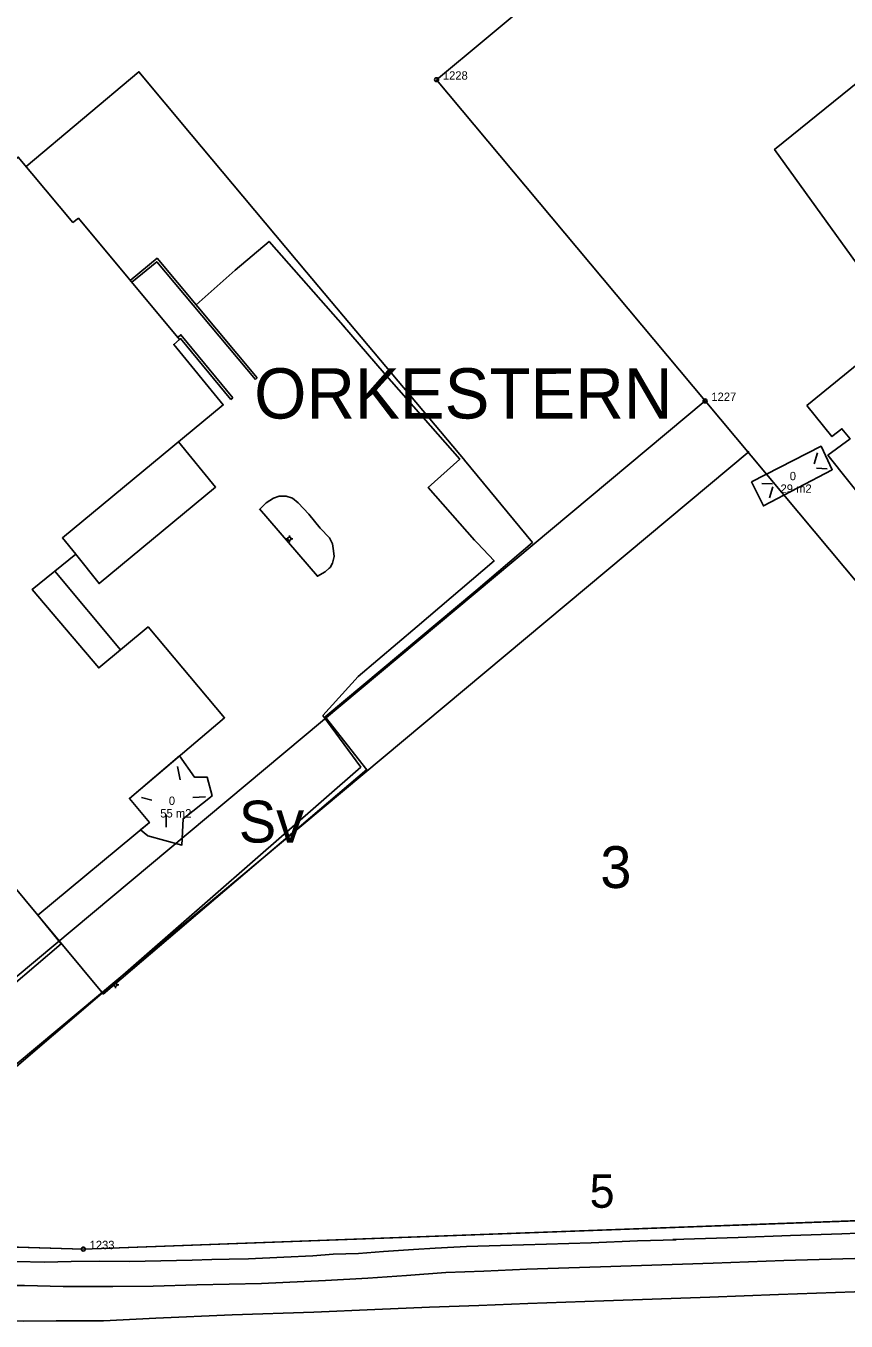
# Model space of a CAD drawing. Extents: x 1517693 to 1518189, y 6494860 to 6495280.
# Drawn here: x 1517838.6 to 1517936.6, y 6494947.7 to 6495102.4 of the extents above; entities that cross this region are included whole.
import ezdxf

# ---------------------------------------------------------------- set-up
doc = ezdxf.new("R2010")
doc.units = 0
for name, color, linetype in [('adress', 7, 'Continuous'), ('allmanbygg_symbollinje', 7, 'Continuous'), ('allmanbyggnad', 7, 'Continuous'), ('allmanbyggnad_nummer', 7, 'Continuous'), ('byggnad_areatext', 7, 'Continuous'), ('fastighetsbeteckning', 7, 'Continuous'), ('gc_vag', 7, 'Continuous'), ('grans', 7, 'Continuous'), ('granspunkt', 7, 'Continuous'), ('granspunkt_text', 7, 'Continuous'), ('kvartersgrans', 7, 'Continuous'), ('kvartersnamn', 7, 'Continuous'), ('parkeringskant', 7, 'Continuous'), ('planteringskant', 7, 'Continuous'), ('rattighet_grans_ANV_EJ', 7, 'Continuous'), ('skarmtak', 7, 'Continuous'), ('staket', 7, 'Continuous'), ('stenmur', 7, 'Continuous'), ('stolpe_belysning', 7, 'Continuous'), ('sv_text', 7, 'Continuous'), ('vagkant', 7, 'Continuous'), ('vagkant_mindre', 7, 'Continuous')]:
    doc.layers.add(name, color=color, linetype=linetype)

msp = doc.modelspace()

# ---------------------------------------------------------------- linework, layer by layer
at = {"layer": 'allmanbygg_symbollinje'}
for p, q in [((1517933.16, 6495051.39), (1517932.74, 6495050.08)), ((1517933.04, 6495049.54), (1517934.3, 6495049.48)), ((1517926.51, 6495047.74), (1517927.77, 6495047.68)), ((1517927.83, 6495047.32), (1517927.41, 6495046)), ((1517856.72, 6495013.92), (1517857.04, 6495012.34)), ((1517852.41, 6495010.21), (1517853.68, 6495009.93)), ((1517860.05, 6495010.31), (1517858.55, 6495010.24)), ((1517855.39, 6495006.7), (1517855.36, 6495008.21))]:
    msp.add_line(p, q, dxfattribs=at)
at = {"layer": 'allmanbyggnad'}
for points in [[(1517795.98, 6495052.03), (1517837.72, 6495086.69), (1517844.24, 6495078.9), (1517844.89, 6495079.4), (1517856.96, 6495064.93), (1517856.28, 6495064.33), (1517862.19, 6495057.11), (1517842.98, 6495041.23), (1517844.57, 6495039.29), (1517839.38, 6495035.07), (1517847.33, 6495025.71), (1517853.22, 6495030.6), (1517862.35, 6495019.75), (1517850.98, 6495010.13), (1517853.38, 6495007.24), (1517840.06, 6494996.19), (1517822.37, 6495017.44), (1517823.84, 6495018.69), (1517795.97, 6495052.03)], [(1517931.88, 6495057.02), (1517968.08, 6495086.54)], [(1517941.88, 6495041.67), (1517934.38, 6495051.09), (1517937.03, 6495053.07), (1517936.06, 6495054.26), (1517934.86, 6495053.33), (1517931.87, 6495057.03)], [(1517925.25, 6495047.92), (1517933.58, 6495052.17), (1517934.9, 6495049.36), (1517926.69, 6495045.04), (1517925.25, 6495047.92)], [(1517850.98, 6495010.13), (1517856.98, 6495015.21), (1517858.75, 6495012.67), (1517860.26, 6495012.67), (1517860.86, 6495010.41), (1517857.4, 6495007.7), (1517857.25, 6495004.55), (1517853.2, 6495005.67), (1517852.31, 6495006.35), (1517853.38, 6495007.24), (1517850.98, 6495010.13)]]:
    msp.add_lwpolyline(points, dxfattribs=at)
at = {"layer": 'gc_vag'}
for points in [[(1517916.26, 6494957.41), (1517911.67, 6494957.3), (1517906.13, 6494957.05), (1517900.78, 6494956.88), (1517895.28, 6494956.74), (1517891.25, 6494956.6)], [(1517939.93, 6494958.28), (1517936.05, 6494958.14), (1517929.92, 6494957.93), (1517923.68, 6494957.69), (1517915.87, 6494957.44)], [(1517891.25, 6494956.6), (1517889.71, 6494956.53), (1517887.5, 6494956.42), (1517884.91, 6494956.25), (1517881.34, 6494956.04), (1517878.32, 6494955.79), (1517875.31, 6494955.69), (1517872.89, 6494955.51), (1517869.43, 6494955.34), (1517865.22, 6494955.16), (1517862.88, 6494955.09)], [(1517862.88, 6494955.09), (1517860.81, 6494955.05), (1517858.46, 6494954.98), (1517854.75, 6494954.91), (1517851, 6494954.84), (1517847.43, 6494954.88), (1517844.03, 6494954.84), (1517840.85, 6494954.74), (1517837.48, 6494954.81), (1517835.56, 6494954.81), (1517834.33, 6494954.91)], [(1517879.46, 6494952.85), (1517884.07, 6494953.16), (1517888.76, 6494953.52), (1517893.31, 6494953.69), (1517898.43, 6494953.9), (1517907.22, 6494954.18)], [(1517907.22, 6494954.18), (1517920.7, 6494954.64), (1517929.14, 6494954.95), (1517938.99, 6494955.23)], [(1517853.81, 6494951.88), (1517859.04, 6494952.04), (1517866.75, 6494952.18), (1517874.38, 6494952.57), (1517879.46, 6494952.85)], [(1517832.31, 6494947.99), (1517832.41, 6494949.71), (1517832.62, 6494951.11), (1517833.29, 6494951.63), (1517833.95, 6494951.95), (1517838.47, 6494951.95), (1517843.09, 6494951.84), (1517849.01, 6494951.84), (1517853.81, 6494951.88)]]:
    msp.add_lwpolyline(points, dxfattribs=at)
at = {"layer": 'grans'}
for p, q in [((1517942.78, 6495142.01), (1517887.66, 6495095.94)), ((1517919.72, 6495057.58), (1517887.66, 6495095.94)), ((1517807.17, 6494963.51), (1517919.72, 6495057.58)), ((1517993.72, 6494969.04), (1517919.72, 6495057.58)), ((1517845.48, 6494956.3), (1517968.3, 6494960.82)), ((1517833.61, 6494956.65), (1517845.48, 6494956.3))]:
    msp.add_line(p, q, dxfattribs=at)
at = {"layer": 'granspunkt'}
for centre in [(1517887.66, 6495095.94), (1517919.72, 6495057.58), (1517845.48, 6494956.3)]:
    msp.add_circle(centre, 0.237, dxfattribs=at)
at = {"layer": 'kvartersgrans'}
msp.add_lwpolyline([(1517810.53, 6494961.99), (1517821.9, 6494958.56), (1517833.61, 6494956.65), (1517845.48, 6494956.3), (1517968.3, 6494960.82), (1517976.46, 6494961.8), (1517984.36, 6494964.1), (1517991.77, 6494967.66)], dxfattribs=at)
at = {"layer": 'parkeringskant'}
msp.add_lwpolyline([(1517964.72, 6495092.99), (1517953.28, 6495108.07), (1517928.01, 6495087.61), (1517943.33, 6495066.36)], dxfattribs=at)
at = {"layer": 'planteringskant'}
msp.add_lwpolyline([(1517866.55, 6495044.64), (1517867.32, 6495045.43), (1517868.17, 6495045.97), (1517868.88, 6495046.21), (1517869.72, 6495046.2), (1517870.45, 6495045.97), (1517871.15, 6495045.43), (1517872.4, 6495044.06), (1517873.76, 6495042.4), (1517874.88, 6495041.24), (1517875.25, 6495040.5), (1517875.34, 6495039.67), (1517875.42, 6495039.01), (1517875.24, 6495038.21), (1517874.94, 6495037.7), (1517874.85, 6495037.62), (1517874.35, 6495037.18), (1517873.43, 6495036.64), (1517866.52, 6495044.68)], dxfattribs=at)
at = {"layer": 'rattighet_grans_ANV_EJ'}
msp.add_line((1517924.99, 6495051.56), (1517819.73, 6494963.58), dxfattribs=at)
at = {"layer": 'skarmtak'}
msp.add_line((1517842.08, 6495037.27), (1517849.92, 6495027.86), dxfattribs=at)
msp.add_lwpolyline([(1517856.86, 6495052.71), (1517861.28, 6495047.29), (1517847.36, 6495035.77), (1517844.54, 6495039.33)], dxfattribs=at)
at = {"layer": 'staket'}
for p, q in [((1517872.13, 6495072.97), (1517858.36, 6495089.39)), ((1517891.06, 6495050.42), (1517872.13, 6495072.97)), ((1517874.36, 6495019.87), (1517892.35, 6495034.9)), ((1517879.35, 6495013.53), (1517874.36, 6495019.87)), ((1517847.87, 6494986.76), (1517879.32, 6495013.57)), ((1517840.06, 6494996.19), (1517847.88, 6494986.75))]:
    msp.add_line(p, q, dxfattribs=at)
for points in [[(1517838.64, 6495085.58), (1517852.12, 6495096.88), (1517858.36, 6495089.39)], [(1517892.34, 6495034.89), (1517899.1, 6495040.69), (1517891, 6495050.5)]]:
    msp.add_lwpolyline(points, dxfattribs=at)
at = {"layer": 'stenmur'}
for p, q in [((1517866.03, 6495060.14), (1517866.24, 6495060.33)), ((1517863.11, 6495057.76), (1517863.35, 6495057.96))]:
    msp.add_line(p, q, dxfattribs=at)
for points in [[(1517851.08, 6495071.97), (1517854.28, 6495074.61), (1517866.25, 6495060.32)], [(1517851.26, 6495071.75), (1517854.24, 6495074.21), (1517866.03, 6495060.14)], [(1517856.79, 6495065.18), (1517857.13, 6495065.48), (1517863.35, 6495057.96)], [(1517856.99, 6495064.94), (1517857.09, 6495065.03), (1517863.11, 6495057.76)]]:
    msp.add_lwpolyline(points, dxfattribs=at)
at = {"layer": 'stolpe_belysning'}
for p, q in [((1517869.88, 6495041.12), (1517869.68, 6495041.12)), ((1517870.08, 6495041.32), (1517870.08, 6495041.52)), ((1517870.08, 6495040.92), (1517870.08, 6495040.72)), ((1517870.28, 6495041.12), (1517870.48, 6495041.12)), ((1517849.12, 6494987.87), (1517848.92, 6494987.87)), ((1517849.32, 6494988.07), (1517849.32, 6494988.27)), ((1517849.52, 6494987.87), (1517849.72, 6494987.87)), ((1517849.32, 6494987.67), (1517849.32, 6494987.47))]:
    msp.add_line(p, q, dxfattribs=at)
for centre in [(1517870.08, 6495041.12), (1517849.32, 6494987.87)]:
    msp.add_circle(centre, 0.2, dxfattribs=at)
at = {"layer": 'vagkant'}
for points in [[(1517907.64, 6494950.12), (1517920.28, 6494950.57), (1517928.48, 6494950.89), (1517939.83, 6494951.27)], [(1517880.27, 6494949.1), (1517886.83, 6494949.38), (1517892.72, 6494949.59), (1517898.57, 6494949.8), (1517907.64, 6494950.12)], [(1517832.31, 6494947.99), (1517834.83, 6494947.82), (1517838.37, 6494947.71), (1517842.24, 6494947.74), (1517847.89, 6494947.75), (1517851.78, 6494947.96), (1517854.13, 6494948.06)], [(1517854.13, 6494948.06), (1517863.27, 6494948.44), (1517873.02, 6494948.78), (1517880.27, 6494949.1)]]:
    msp.add_lwpolyline(points, dxfattribs=at)
at = {"layer": 'vagkant_mindre'}
for points in [[(1517858.95, 6495069.04), (1517863.6, 6495073.2), (1517867.67, 6495076.63), (1517876.78, 6495066.27)], [(1517876.44, 6495066.66), (1517881.4, 6495060.9), (1517890.42, 6495050.64), (1517886.67, 6495047.26), (1517892.17, 6495040.97)], [(1517891.87, 6495041.32), (1517894.53, 6495038.47), (1517885.33, 6495030.66), (1517878.31, 6495024.69), (1517874.09, 6495020.04)], [(1517814.6, 6494958.94), (1517835.57, 6494976.43), (1517848.02, 6494987.1), (1517878.6, 6495013.87), (1517874.09, 6495020.04)], [(1517836.85, 6494987.68), (1517842.85, 6494992.77), (1517840.06, 6494996.19)]]:
    msp.add_lwpolyline(points, dxfattribs=at)

# ---------------------------------------------------------------- texts
at = {"layer": 'adress'}
msp.add_text('5', height=4, rotation=0.0021, dxfattribs=at).set_placement((1517905.94, 6494961.24))
at = {"layer": 'allmanbyggnad_nummer'}
for p in [(1517929.83, 6495048.11), (1517855.69, 6495009.34)]:
    msp.add_text('0', height=1, dxfattribs=at).set_placement(p)
at = {"layer": 'byggnad_areatext'}
for s, p in [('29 m2', (1517928.73, 6495046.61)), ('55 m2', (1517854.67, 6495007.84))]:
    msp.add_text(s, height=1, dxfattribs=at).set_placement(p)
at = {"layer": 'fastighetsbeteckning'}
msp.add_text('3', height=5, rotation=0.0021, dxfattribs=at).set_placement((1517907.21, 6494999.42))
at = {"layer": 'granspunkt_text'}
for s, p in [('1228', (1517888.41, 6495095.94)), ('1227', (1517920.47, 6495057.58)), ('1233', (1517846.23, 6494956.3))]:
    msp.add_text(s, height=1, dxfattribs=at).set_placement(p)
at = {"layer": 'kvartersnamn'}
msp.add_text('ORKESTERN', height=6, rotation=0.0021, dxfattribs=at).set_placement((1517865.88, 6495055.48))
at = {"layer": 'sv_text'}
msp.add_text('Sv', height=5, rotation=0.0021, dxfattribs=at).set_placement((1517864.05, 6495004.85))

doc.saveas('drawing.dxf')
